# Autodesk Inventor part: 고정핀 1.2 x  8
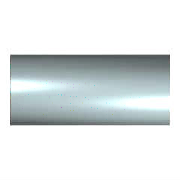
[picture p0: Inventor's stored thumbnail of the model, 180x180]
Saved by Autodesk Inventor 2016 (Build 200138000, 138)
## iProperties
IsCustomPart: 1
Created: 2012-02
Part Number: 고정핀 1.2 x  8
Material: 강철, 연강
Description: 평행 핀
Document SubType Name: Modeling
Standard: KS B 1320
Designer: P15F
Standards Organization: KS
Language: ko-KR
Size Designation: C 1.2 x  8
Categories: <MemberInstance><Categories><Category DisplayName="조임쇠" InternalName="e4da775c-781d-43d5-af7c-5136215cf5a6" Mnemonic="FSTN"><Category DisplayName="핀" InternalNa
Density: 1 g/cm^3
Appearance: 노란색
Author: P15F
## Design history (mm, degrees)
sketch "스케치1"
  geometry: C1 r 0.6 at (0, 0); 1 further point
  constraints: 1 centre point, 1 coincident
  dimensions: "d1" = 1.2 diameter of C1 (= NND)
extrude "본체" new body sketch "스케치1" distance "d2" = 8 (= NLG); taper "d3" = 0 deg
node "작업 평면1"
body "Solid1"
other parameters: "NND" = 1.2 [user parameter; used in 1 equation term], "NLG" = 8 [user parameter; used in 1 equation term], "d8" = 0, "d9" = 0, "d10" = 0
